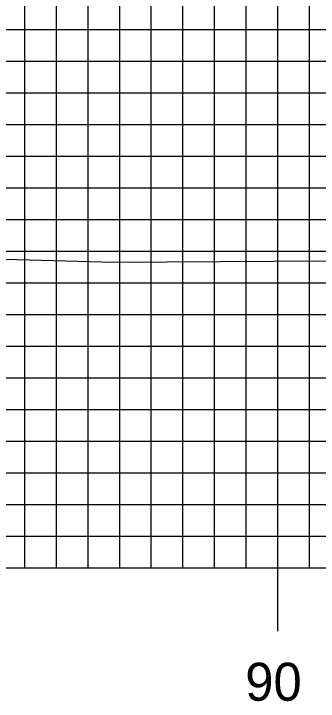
# Model space of a CAD drawing. Extents: x 1781467 to 1781810, y 442591 to 442811.
# Drawn here: x 1781534.06 to 1781543.69, y 442714.45 to 442736.17 of the extents above; entities that cross this region are included whole.
import ezdxf

# ---------------------------------------------------------------- set-up
doc = ezdxf.new("R2010")
doc.units = 0
for name, color, linetype in [('H_V ANNOTATION', 7, 'Continuous'), ('MAJOR', 7, 'Continuous'), ('MINOR', 7, 'Continuous'), ('S_Roadway_Centerline', 7, 'Continuous')]:
    doc.layers.add(name, color=color, linetype=linetype)

msp = doc.modelspace()

# ---------------------------------------------------------------- linework, layer by layer
at = {"layer": 'MAJOR'}
for p, q in [((1781542.408, 442718.665), (1781542.408, 442753.665)), ((1781492.408, 442733.665), (1781772.408, 442733.665)), ((1781492.408, 442728.665), (1781772.408, 442728.665)), ((1781492.408, 442723.665), (1781772.408, 442723.665)), ((1781492.408, 442718.665), (1781772.408, 442718.665)), ((1781492.408, 442718.665), (1781772.408, 442718.665)), ((1781542.408, 442716.661), (1781542.408, 442718.665))]:
    msp.add_line(p, q, dxfattribs=at)
at = {"layer": 'MINOR'}
for p, q in [((1781534.408, 442718.665), (1781534.408, 442753.665)), ((1781535.408, 442718.665), (1781535.408, 442753.665)), ((1781536.408, 442718.665), (1781536.408, 442753.665)), ((1781537.408, 442718.665), (1781537.408, 442753.665)), ((1781538.408, 442718.665), (1781538.408, 442753.665)), ((1781539.408, 442718.665), (1781539.408, 442753.665)), ((1781540.408, 442718.665), (1781540.408, 442753.665)), ((1781541.408, 442718.665), (1781541.408, 442753.665)), ((1781543.408, 442718.665), (1781543.408, 442753.665)), ((1781492.408, 442735.665), (1781772.408, 442735.665)), ((1781492.408, 442734.665), (1781772.408, 442734.665)), ((1781492.408, 442732.665), (1781772.408, 442732.665)), ((1781492.408, 442731.665), (1781772.408, 442731.665)), ((1781492.408, 442730.665), (1781772.408, 442730.665)), ((1781492.408, 442729.665), (1781772.408, 442729.665)), ((1781492.408, 442727.665), (1781772.408, 442727.665)), ((1781492.408, 442726.665), (1781772.408, 442726.665)), ((1781492.408, 442725.665), (1781772.408, 442725.665)), ((1781492.408, 442724.665), (1781772.408, 442724.665)), ((1781492.408, 442722.665), (1781772.408, 442722.665)), ((1781492.408, 442721.665), (1781772.408, 442721.665)), ((1781492.408, 442720.665), (1781772.408, 442720.665)), ((1781492.408, 442719.665), (1781772.408, 442719.665))]:
    msp.add_line(p, q, dxfattribs=at)
at = {"layer": 'S_Roadway_Centerline'}
msp.add_lwpolyline([(1781492.408, 442729.342), (1781498.389, 442729.01), (1781507.586, 442728.75), (1781513.832, 442728.85), (1781524.101, 442728.723), (1781527.639, 442728.582), (1781537.224, 442728.321), (1781545.64, 442728.366), (1781559.35, 442728.108), (1781569.071, 442727.794), (1781574.556, 442727.88), (1781583.781, 442728.007), (1781593.87, 442727.964), (1781606.484, 442727.726)], dxfattribs=at)

# ---------------------------------------------------------------- texts
at = {"layer": 'H_V ANNOTATION'}
msp.add_text('90', height=1.2, dxfattribs=at).set_placement((1781541.38, 442714.465))

doc.saveas('drawing.dxf')
